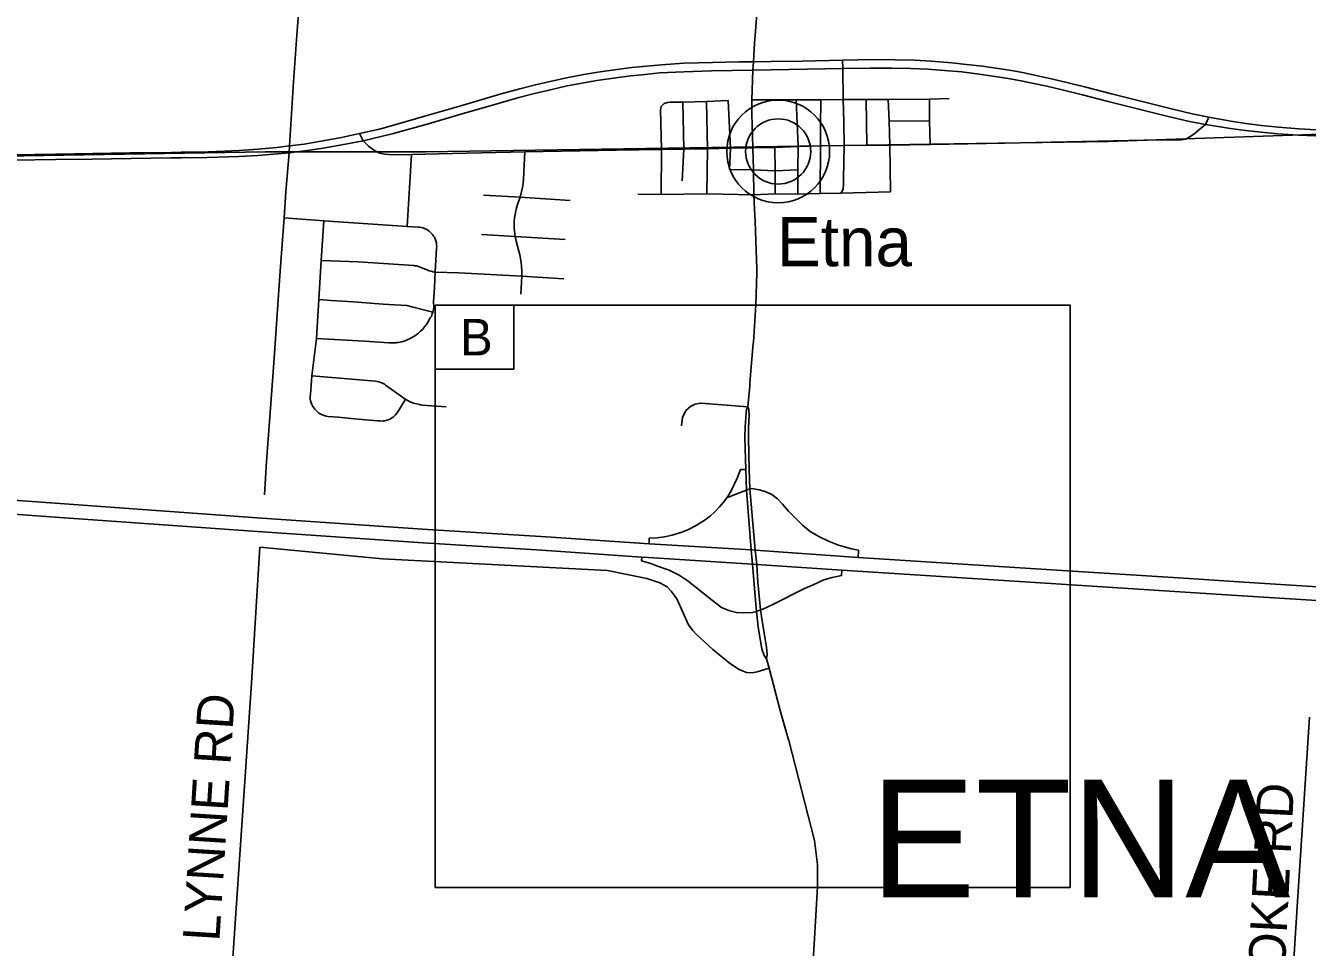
# Model space of a CAD drawing. Extents: x 1880545 to 1948545, y 79309 to 723051.
# Drawn here: x 1911747 to 1921540, y 706837 to 713881 of the extents above; entities that cross this region are included whole.
import ezdxf

# ---------------------------------------------------------------- set-up
doc = ezdxf.new("R2010")
doc.units = 0
for name, color, linetype in [('GM_X_Interchange_Ramps', 7, 'Continuous'), ('GM_X_Interstate_Route', 7, 'Continuous'), ('GM_X_Rail_Line', 7, 'Continuous'), ('GM_X_State_Route', 7, 'Continuous'), ('GM_X_Township_Road', 7, 'Continuous'), ('GM_X_Township_Text', 7, 'Continuous'), ('GM_X_Unincorporated', 7, 'Continuous'), ('GM_X_Unincorporated_Location', 7, 'Continuous'), ('GM_X_Unincorporated_Text', 7, 'Continuous'), ('GM_X_US_Route', 7, 'Continuous'), ('SH_Text', 7, 'Continuous')]:
    doc.layers.add(name, color=color, linetype=linetype)

msp = doc.modelspace()

# ---------------------------------------------------------------- linework, layer by layer
at = {"layer": 'GM_X_Interchange_Ramps'}
for points in [[(1917248.6, 710488.4), (1917209.4, 710488.7), (1917183.4, 710421.9), (1917137.7, 710324.7), (1917111.9, 710283.4), (1917078.7, 710238.4), (1917048.6, 710202.7), (1917014.8, 710168.4), (1916975.6, 710133.3), (1916930.8, 710100), (1916864.4, 710059.4), (1916810.5, 710030.9), (1916759.3, 710008.8), (1916686, 709986.8), (1916628.2, 709975.5), (1916570.7, 709965.5), (1916511.9, 709963.8), (1916510, 709920.1)], [(1917280.1, 710341.6), (1917254.5, 710330.5), (1917213.3, 710314.9), (1917173.7, 710300.7), (1917142.3, 710288.3), (1917120.5, 710278.3), (1917111.9, 710283.4)], [(1918107.3, 709816.5), (1918109.4, 709871.8), (1918056.2, 709883.7), (1917957.8, 709910.5), (1917881.8, 709940.3), (1917807.2, 709976.1), (1917741.6, 710014.9), (1917682, 710062.7), (1917576, 710171.5), (1917529.7, 710223.1), (1917490.9, 710263.6), (1917447.5, 710298.3), (1917398.2, 710320.9), (1917351.3, 710334.2), (1917295.8, 710344.1), (1917280.1, 710341.6)], [(1916453.6, 709819.7), (1916451.5, 709791.6), (1916523.3, 709771.5), (1916574.8, 709750.9), (1916662.8, 709719.6), (1916738.9, 709682.3), (1916808.9, 709636), (1916859.8, 709595.8)], [(1917361.1, 709415.7), (1917373.3, 709420.1), (1917461.4, 709459.3), (1917697, 709579.8), (1917764.2, 709608.1), (1917845.1, 709646.5), (1917909.3, 709664.4), (1917980.6, 709677.9), (1917983.3, 709718.4)], [(1916859.8, 709595.8), (1916995.3, 709488.4), (1917063.9, 709433.2), (1917127.3, 709409.5), (1917177.2, 709395.9), (1917234.7, 709392.5), (1917300.7, 709396.5), (1917332.1, 709403.7), (1917361.1, 709415.7)]]:
    msp.add_lwpolyline(points, dxfattribs=at)
at = {"layer": 'GM_X_Interstate_Route'}
msp.add_line((1921053.7, 709628.8), (1921618.3, 709592.4), dxfattribs=at)
for points in [[(1901555.6, 710973.1), (1902366.6, 710916.4), (1903998.5, 710800.7), (1905618, 710687.2), (1906999.3, 710587.7), (1908168.8, 710505.6), (1909395.1, 710418.8), (1910619, 710332.1), (1911124, 710292.8), (1912006.9, 710227.9), (1913551.3, 710116.9), (1914818, 710030.1), (1915723.8, 709974.6), (1916510, 709920.1), (1917290.8, 709873.9), (1917320.8, 709872.1), (1918107.3, 709816.5), (1919464.3, 709728.6), (1920634.3, 709655.9), (1921053.7, 709628.8)], [(1901416.6, 710877.5), (1902078.9, 710829.4), (1902917.1, 710764.9), (1903996.4, 710690.1), (1905616, 710576.7), (1906997.2, 710477.2), (1908166.8, 710395.1), (1909393, 710308.3), (1910617, 710221.6), (1911089.1, 710188.4), (1911972.8, 710125.6), (1913517.1, 710014.5), (1914783.9, 709927.7), (1915689.7, 709872.2), (1916453.6, 709819.7), (1916505.3, 709816.7), (1917218.6, 709769.7)], [(1917218.6, 709769.7), (1917300.1, 709764.3), (1917332.3, 709762.2), (1917983.3, 709718.4), (1918103.6, 709712.1), (1919460.5, 709624.2), (1921001.8, 709525.6)], [(1921001.8, 709525.6), (1921610.9, 709486.7), (1921653.5, 709483.9)]]:
    msp.add_lwpolyline(points, dxfattribs=at)
at = {"layer": 'GM_X_Rail_Line'}
msp.add_lwpolyline([(1889655.8, 712431.1), (1890757.3, 712458.2), (1898416.8, 712647.1), (1903434.4, 712740.7), (1904815.9, 712771.4), (1913576.2, 712915.6), (1914801.4, 712915.6), (1920018.8, 712994.7), (1921941.6, 713063), (1924552.9, 713124.1), (1928206.5, 713205.6)], dxfattribs=at)
at = {"layer": 'GM_X_State_Route'}
for p, q in [((1917283.4, 711180.8), (1917305.8, 711451.7)), ((1917265.2, 710967.2), (1917278.9, 711126.9)), ((1917427.6, 708971.1), (1917408.3, 709042.1)), ((1917568.4, 708449.5), (1917565.5, 708459.7))]:
    msp.add_line(p, q, dxfattribs=at)
for points in [[(1917325, 713870), (1917338.5, 714052), (1917361.5, 714406.9)], [(1917301.6, 713539.9), (1917309, 713603.9), (1917315.8, 713747), (1917325, 713870)], [(1917296.3, 713208.2), (1917294, 713313), (1917301.6, 713539.9)], [(1917316.1, 712479.1), (1917311.5, 712588.7), (1917307.8, 712780.1), (1917302.1, 712946.3), (1917296.3, 713208.2)], [(1917305.8, 711451.7), (1917306.7, 711462.6), (1917325.2, 711747.1), (1917333, 711992.7), (1917332.6, 712019.7), (1917320, 712386), (1917316.1, 712479.1)], [(1917278.9, 711126.9), (1917280.2, 711142.9), (1917283.4, 711180.8)], [(1917332.1, 709403.7), (1917316.3, 709578.3), (1917300.1, 709764.3), (1917290.8, 709873.9), (1917254.5, 710330.5), (1917248.6, 710488.4), (1917241.2, 710731.9), (1917245.1, 710816.2), (1917250.9, 710921.3), (1917254.8, 710947.9), (1917265.2, 710967.2)], [(1917342.2, 709622.3), (1917332.3, 709762.2), (1917320.8, 709872.1), (1917280.1, 710341.6), (1917274.9, 710487.7), (1917269.7, 710731.5), (1917270.3, 710810.2), (1917273.7, 710900), (1917272, 710948), (1917265.2, 710967.2)], [(1917361.1, 709415.7), (1917345.5, 709575.7), (1917342.2, 709622.3)], [(1917408.3, 709042.1), (1917412.1, 709074.3), (1917407.5, 709132.2), (1917388.4, 709237.6), (1917368.7, 709366.1), (1917361.1, 709415.7)], [(1917408.3, 709042.1), (1917390.1, 709066.2), (1917372.8, 709117.7), (1917353.7, 709223.1), (1917343.8, 709287.4), (1917332.1, 709403.7)], [(1917565.5, 708459.7), (1917512.7, 708648.2), (1917427.6, 708971.1)], [(1917724.5, 705792.3), (1917745.3, 706424.2), (1917797.4, 707299.2), (1917797.4, 707469.3), (1917774.8, 707653.3), (1917576.9, 708419), (1917568.4, 708449.5)]]:
    msp.add_lwpolyline(points, dxfattribs=at)
at = {"layer": 'GM_X_Township_Road'}
for p, q in [((1917821.1, 713109.2), (1917822.1, 713313.1)), ((1918173.1, 712966.9), (1918168.4, 713317.3)), ((1918651.8, 713320.1), (1918802, 713323.8)), ((1918345, 713150.9), (1918653.8, 713153.4)), ((1914662.8, 712346.7), (1914696, 712895.9)), ((1916602.6, 712590.3), (1916604.4, 712929.8)), ((1915245, 712586.4), (1915525.6, 712569.9)), ((1915525.6, 712569.9), (1915908, 712545.8)), ((1915229.4, 712285.3), (1915486.4, 712270.3)), ((1915486.4, 712270.3), (1915867.7, 712246.9))]:
    msp.add_line(p, q, dxfattribs=at)
for points in [[(1913761, 712909.6), (1913763.9, 712961.6), (1913794.1, 713451), (1913818.8, 713807.7), (1913846, 714173.9), (1913855.9, 714310.9), (1913856.8, 714331.9), (1913895.8, 715162.1), (1913937.8, 715745.4), (1913951.2, 715762.5), (1913960.2, 715880), (1913960.2, 715924.2), (1913977.5, 716194), (1913972.6, 716223.4), (1914046.4, 717097.8), (1914089.2, 717898.5), (1914127.1, 718463)], [(1917997, 713140.4), (1917993.4, 713316.3), (1917990.9, 713554), (1917988.8, 713617.1)], [(1916604.4, 712929.8), (1916604.4, 712934.7), (1916597.6, 713236.7), (1916603.3, 713264)], [(1916603.3, 713264), (1916626, 713285.5), (1916649.8, 713293.5), (1916670.3, 713295.8), (1916769.1, 713295.8), (1916949.6, 713302.5), (1917115.4, 713309.4)], [(1916763.9, 712694.1), (1916774.7, 712936.9), (1916769.1, 713295.8)], [(1916952.2, 712596.3), (1916957.6, 712940.3), (1916949.6, 713302.5)], [(1917124.5, 712781), (1917131.3, 712946), (1917115.4, 713309.4)], [(1917294, 713313), (1917633.6, 713315.3), (1917822.1, 713313.1), (1917993.4, 713316.3), (1918168.4, 713317.3), (1918338, 713316.6), (1918651.8, 713320.1)], [(1917646.6, 712593.6), (1917647.5, 712779.5), (1917649.4, 712957.6), (1917633.6, 713315.3)], [(1918354.2, 712611.7), (1918348.7, 712968.5), (1918345, 713150.9), (1918338, 713316.6)], [(1918658.1, 712973.2), (1918653.8, 713153.4), (1918651.8, 713320.1)], [(1914296.4, 713055.8), (1914326.4, 713001.6), (1914366.7, 712960.5), (1914411.9, 712928.1), (1914454, 712906.7), (1914488.9, 712898.2), (1914551.8, 712894.8), (1914696, 712895.9), (1915008.4, 712905.1), (1915561.8, 712916.1), (1916261.3, 712928.9), (1916604.4, 712934.7), (1916774.7, 712936.9), (1916957.6, 712940.3), (1917131.3, 712946), (1917302.1, 712946.3), (1917470.6, 712950.3), (1917649.4, 712957.6), (1917820.3, 712961.3), (1918000.6, 712964.5), (1918173.1, 712966.9), (1918348.7, 712968.5), (1918658.1, 712973.2), (1919228.4, 712983.5), (1920292.5, 713004.9), (1920452.3, 713008.8), (1920541.7, 713008.8), (1920578.1, 713008.8), (1920609.7, 713014.4), (1920642.9, 713030.2), (1920682.5, 713058.6), (1920717.3, 713088.7), (1920762.2, 713126.7), (1920787.7, 713181.1)], [(1917978.5, 712599.8), (1917992.7, 712633), (1917995.1, 712671), (1917996.7, 712712.2), (1918000.6, 712964.5), (1917997, 713140.4)], [(1917816.6, 712598.8), (1917820.3, 712961.3), (1917821.1, 713109.2)], [(1917473.4, 712594.5), (1917473.4, 712772.2), (1917470.6, 712950.3)], [(1913571, 710295.6), (1913587.1, 710551), (1913616.8, 710957.5), (1913648.5, 711376.6), (1913669.2, 711676.9), (1913691.9, 712007.8), (1913723, 712412), (1913734.7, 712609.8), (1913761, 712909.6)], [(1915561.8, 712916.1), (1915553.7, 712760.7), (1915550.2, 712702.7), (1915544.4, 712657.4), (1915525.6, 712569.9), (1915508.5, 712520.7), (1915498.3, 712487.8), (1915492.6, 712465.4), (1915487.1, 712437.3), (1915483.1, 712412.8), (1915480.1, 712380.5), (1915479.2, 712355.1), (1915480.1, 712337.8), (1915481.3, 712310.9), (1915486.4, 712270.3), (1915490, 712257.1), (1915494.3, 712234.1), (1915514.7, 712157.6), (1915521.8, 712128.3), (1915534, 712070.5), (1915536.5, 712043.6), (1915538.5, 712004.6), (1915537.7, 711965.4), (1915529.5, 711829.5)], [(1917124.5, 712781), (1917307.8, 712780.1), (1917473.4, 712772.2), (1917647.5, 712779.5)], [(1916424.4, 712592.6), (1916602.6, 712590.3), (1916952.2, 712596.3), (1917311.5, 712588.7), (1917473.4, 712594.5), (1917646.6, 712593.6), (1917816.6, 712598.8), (1917978.5, 712599.8), (1918354.2, 712611.7)], [(1913723, 712412), (1914024.8, 712389), (1914662.8, 712346.7), (1914747.8, 712341.7), (1914757.9, 712340.8), (1914768.7, 712338.7), (1914782.1, 712335.4), (1914789.3, 712333.1), (1914795.3, 712330.5), (1914805.1, 712326.1), (1914812.3, 712322.1), (1914821, 712316.7), (1914830.6, 712309.4), (1914840.6, 712301.4), (1914856.4, 712283.9), (1914860.8, 712278.3), (1914864, 712273.3), (1914867.7, 712267.3), (1914871.9, 712259.9), (1914875.6, 712251.6), (1914878.4, 712244.8), (1914881.2, 712235.9), (1914883.5, 712227.9), (1914884.9, 712220.8), (1914886.3, 712212.4), (1914887.1, 712202.4), (1914887.6, 712192.7), (1914887.1, 712181.9), (1914876, 711997.9), (1914870.3, 711879), (1914863.8, 711769.7), (1914864.9, 711728.3), (1914861.9, 711712.2), (1914857.2, 711692), (1914853.9, 711679.1), (1914846.5, 711658.7), (1914836.6, 711648.5), (1914828.3, 711630.9), (1914818.4, 711612.2), (1914809.1, 711597.8), (1914795.3, 711578.5), (1914778.5, 711559.9), (1914764.4, 711544.9), (1914743.3, 711525.6), (1914731.7, 711517), (1914720.3, 711509.9), (1914703.5, 711499.5), (1914680.7, 711486.9), (1914668, 711481.6), (1914657.1, 711477.4), (1914646, 711472.8), (1914635.6, 711469.3), (1914622.1, 711465.7), (1914609.4, 711462.9), (1914596.3, 711460.2), (1914583.5, 711458.4), (1914574.2, 711457.3), (1914562.7, 711456.2), (1914552.4, 711455.8), (1914521.5, 711456.4), (1914334.8, 711469), (1913970, 711491)], [(1913956.1, 710949.4), (1913947.9, 710959.3), (1913940.6, 710971), (1913932.4, 710986.6), (1913927.6, 710998.9), (1913924.1, 711012.6), (1913921.6, 711025.9), (1913920.3, 711039.3), (1913921.2, 711049.4), (1913921.9, 711061.1), (1913932.7, 711203.8), (1913970, 711491), (1913987, 711787.2), (1914005.9, 712086.9), (1914024.8, 712389)], [(1914005.9, 712086.9), (1914288.3, 712076.9), (1914712.4, 712046.9), (1914721.4, 712046.4), (1914727.4, 712045.7), (1914732.9, 712044.6), (1914740.6, 712042.9), (1914747.9, 712040.7), (1914757.2, 712037.4), (1914777.9, 712028.8), (1914813.3, 712014.8), (1914831, 712008.3), (1914844.3, 712003.8), (1914852.1, 712001.7), (1914858.2, 712000.3), (1914876, 711997.9), (1915056.3, 711991.8), (1915537.7, 711965.4), (1915858.4, 711945.6)], [(1913987, 711787.2), (1914081.3, 711780.9), (1914248.2, 711770.1), (1914477.9, 711753.1), (1914566.7, 711747.7), (1914660, 711741.4), (1914698.6, 711733.3), (1914857.2, 711692)], [(1913932.7, 711203.8), (1914419.6, 711162.8), (1914432.5, 711161.4), (1914445.4, 711158.3), (1914456.8, 711154.7), (1914467.2, 711150.8), (1914477.8, 711145.5), (1914487.5, 711140), (1914495.6, 711134.1), (1914626.2, 711040.6), (1914637.7, 711032.8), (1914648.2, 711025.8), (1914668.8, 711014.5), (1914690.7, 711004.4), (1914711.2, 710997), (1914733.8, 710990.2), (1914756.1, 710984.8), (1914764.3, 710983.8), (1914780.1, 710981.8), (1914960.4, 710967.3)], [(1913956.1, 710949.4), (1913978.5, 710926.9), (1913987.5, 710920.1), (1913998.3, 710913.3), (1914011.8, 710907), (1914027.1, 710901.1), (1914042, 710897.3), (1914057.4, 710894.8), (1914135.4, 710888.5), (1914258.3, 710877.1), (1914404, 710864), (1914432.4, 710861.2), (1914451.9, 710860), (1914465.8, 710859.4), (1914479.2, 710860.4), (1914490.9, 710861.8), (1914502.2, 710864.3), (1914514.2, 710867.8), (1914524.3, 710871.7), (1914533.3, 710875.7), (1914545.1, 710882.7), (1914554.5, 710889), (1914563.1, 710895.6), (1914572.9, 710906.6), (1914583.4, 710919.5), (1914594.5, 710936.8), (1914648.2, 711025.8)], [(1916757.5, 710823.4), (1916765.7, 710887.6), (1916790.2, 710939.4), (1916825.7, 710970.8), (1916861.2, 710988.6), (1916904.9, 710996.8), (1917265.2, 710967.2)], [(1913294.3, 706235.1), (1913472.4, 708857.2), (1913537, 709895.1)], [(1913537, 709895.1), (1914474, 709806.8), (1916193.2, 709716.2), (1916492, 709655.1), (1916592.5, 709623.3), (1916649.4, 709593.1), (1916678.7, 709558.8), (1916708.8, 709518.6), (1916724.7, 709496), (1916811.4, 709302.9), (1916843.2, 709259.4), (1916870.8, 709230.1), (1916996.4, 709113.7), (1917121.1, 709010.7), (1917193.1, 708963.8), (1917229.1, 708947), (1917255, 708938.6), (1917297.7, 708935.3), (1917337, 708942), (1917427.6, 708971.1)], [(1921285.9, 704417.2), (1921359.4, 705538.6), (1921461.2, 707146.6), (1921555.7, 708597)]]:
    msp.add_lwpolyline(points, dxfattribs=at)
at = {"layer": 'GM_X_Unincorporated'}
for radius in [392.8, 249]:
    msp.add_circle((1917496.6, 712919.8), radius, dxfattribs=at)
at = {"layer": 'GM_X_Unincorporated_Location'}
msp.add_line((1917496.6, 712919.8), (1917496.6, 712919.8), dxfattribs=at)
at = {"layer": 'GM_X_US_Route'}
for points in [[(1912934.6, 712914.1), (1913142.9, 712917.8), (1913379.6, 712926.4), (1913522.7, 712936.4), (1913666.2, 712950.1), (1913763.9, 712961.6), (1913874.9, 712976.1), (1913988.8, 712995.3), (1914159, 713026.2), (1914296.4, 713055.8), (1914449.2, 713091.2), (1914567.8, 713124), (1914803.6, 713191), (1915070.8, 713268.5), (1915380.1, 713358.7), (1915522.9, 713398.8), (1915642.8, 713428.7), (1915764.9, 713457.7), (1915892.9, 713485.9), (1916011, 713508.1), (1916117.8, 713524.9), (1916262.8, 713546), (1916378.2, 713561.4), (1916463.1, 713569.8), (1916604.7, 713582.6), (1916776.4, 713593.4), (1916994.8, 713598.7), (1917195, 713603.3), (1917309, 713603.9)], [(1914326.4, 713001.6), (1914548.3, 713053.8), (1914796.1, 713123.6), (1915063.6, 713201.4), (1915373.9, 713291.3), (1915515, 713331.1), (1915635.8, 713362.4), (1915756.7, 713391.3), (1915885.5, 713421.9), (1916110.4, 713460.8), (1916255.4, 713482), (1916370.8, 713497.4), (1916455.7, 713505.8), (1916593.1, 713519.4), (1916774.7, 713528.5), (1916987.4, 713534.6), (1917301.6, 713539.9)], [(1917301.6, 713539.9), (1917990.9, 713554), (1918197.7, 713556.6), (1918364.4, 713557.4), (1918511, 713554.8), (1918640.2, 713549.1), (1918798.4, 713536.2), (1918899.3, 713527), (1919031.8, 713510.5), (1919154, 713492.6), (1919268.9, 713475), (1919351.5, 713459.4), (1919436.7, 713442.1), (1919549.2, 713419.1), (1919665.3, 713391.1), (1919821.7, 713352.8), (1920017.2, 713302.5), (1920283.9, 713234.7), (1920476.3, 713186.4), (1920640.3, 713149.8), (1920762.2, 713126.7)], [(1917309, 713603.9), (1917442.4, 713606.5), (1917680.6, 713610.8), (1917988.8, 713617.1), (1918222.5, 713621.1), (1918390.2, 713620.8), (1918539.6, 713616.6), (1918666.3, 713610), (1918822.7, 713597.9), (1918935.5, 713585.3), (1919057.2, 713570.7), (1919178.1, 713553.8), (1919293.7, 713534.7), (1919374.8, 713519.6), (1919455.4, 713503.5), (1919571.5, 713478.3), (1919691.1, 713449.6), (1919847, 713411.3), (1920043.2, 713360.7), (1920309.4, 713293.7), (1920502.4, 713245), (1920660.6, 713207.5), (1920787.7, 713181.1), (1920955.2, 713152.1), (1921069.8, 713134.5), (1921189, 713119.1), (1921319.2, 713104.5), (1921475.3, 713091.7), (1921609.6, 713083.6)], [(1920762.2, 713126.7), (1920952.3, 713095.9), (1921066.8, 713080.4), (1921186.6, 713066), (1921313.3, 713054.5), (1921472.8, 713043.4), (1921601, 713037.8), (1921713.1, 713036.7)], [(1912937.5, 712871.6), (1913133, 712874.2), (1913375.8, 712881.3), (1913520.1, 712889.1), (1913761, 712909.6), (1913896.6, 712927.1), (1914019.3, 712946), (1914190.2, 712974.9), (1914326.4, 713001.6)], [(1911437.1, 712849.8), (1911655.3, 712851.8), (1911974.6, 712857.4), (1912254.5, 712861.1), (1912550.9, 712865.7), (1912855.2, 712870.5), (1912937.5, 712871.6)], [(1911658.1, 712894.6), (1911977.5, 712899.4), (1912259.8, 712904.2), (1912543.9, 712908.7), (1912861.8, 712912.8), (1912934.6, 712914.1)]]:
    msp.add_lwpolyline(points, dxfattribs=at)
at = {"layer": 'SH_Text'}
msp.add_lwpolyline([(1914876, 711744.8), (1919727.7, 711744.8), (1919727.7, 707295), (1914876, 707295)], close=True, dxfattribs=at)
msp.add_lwpolyline([(1914876, 711255.9), (1915476, 711255.9), (1915476, 711744.8)], dxfattribs=at)

# ---------------------------------------------------------------- texts
at = {"layer": 'GM_X_Township_Text'}
msp.add_text('ETNA', height=900, rotation=0.00001, dxfattribs=at).set_placement((1918200, 707218.3))
at = {"layer": 'GM_X_Unincorporated_Text'}
msp.add_text('Etna', height=375, rotation=0.00001, dxfattribs=at).set_placement((1917487.1, 712042.4))
at = {"layer": 'SH_Text'}
msp.add_text('B', height=280, dxfattribs=at).set_placement((1915065.6, 711360.3))
for s, rotation, p in [('LYNNE RD', 86.40079, (1913226.6, 706878.2)), ('SMOKE RD', 87.13945, (1921339.5, 706092.1))]:
    msp.add_text(s, height=280, rotation=rotation, dxfattribs=at).set_placement(p)

doc.saveas('drawing.dxf')
